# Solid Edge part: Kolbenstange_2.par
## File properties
Username: bmolnar
Dokumentum tartalom típus: 0
Author: bmolnar
Last saved by: bmolnar
Revision: 96
Sűrűség: 0,000 kg/m^3
Pontosság: 0,990
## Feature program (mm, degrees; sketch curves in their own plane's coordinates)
base feature "unnamed BaseFeature 1"
thread "unnamed Thread 1"
chamfer "Letörés_1"  SetBackValue2 = 20 deg
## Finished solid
Body 1: solid body, 19 faces, 31 edges, 16 vertices.
  Faces by surface: plane 8, cylinder 5, cone 3, torus 3
  Edges by curve: circle 18, line 8, curve on surface 3, ellipse 2
Bounding box of the edges (mm; curved faces can reach further): 100.000 x 100.000 x 2632.500, from (-50, -50, -78.75) to (50, 50, 2553.75).
Cylindrical faces by radius (mm): R8.75 x1, R10 x1, R12.25 x1, R12.5 x1, R50 x1
Conical faces (half-angle, radius in mm at the cone's reference point): 20 deg R8.7989 x1, 30 deg R12.375 x1, 60 deg R9.375 x1
Toroidal faces (ring radius, tube radius in mm): R9.15 r0.4 x2, R10.45 r1.8 x1
Planar faces by outward normal: +x 1, +z 3, -x 1, -z 1, oblique 2
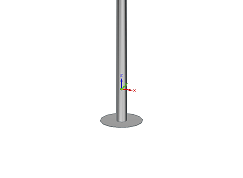
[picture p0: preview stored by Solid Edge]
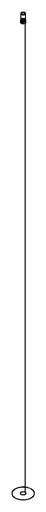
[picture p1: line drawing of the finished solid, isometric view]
